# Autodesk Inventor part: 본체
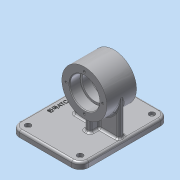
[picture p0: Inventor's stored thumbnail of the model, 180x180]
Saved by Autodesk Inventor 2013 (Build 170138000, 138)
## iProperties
Created: 2019-09
Part Number: 본체
Material: 알루미늄 6061
Document SubType Name: Modeling
Designer: Administrator
Density: 2.71 g/cm^3
Mass: 556.668 g
Surface Area: 495.884 cm^2
Volume: 205.413 cm^3
Author: Administrator
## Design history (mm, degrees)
sketch "스케치1"
  geometry: C1 r 32 at (0, 0); 1 further point
  constraints: 1 centre point, 1 coincident
  dimensions: "d0" = 64 diameter of C1
extrude "돌출1" new body sketch "스케치1" stored distance "d1" = 42; taper "d2" = 0 deg
hole "구멍1" diameter "d5" = 36; stored, may be unused: countersink angle "d9" = 90 deg, drill point angle "d11" = 118 deg; dims "d6" = 6, "d7" = 42, "d8" = 15, "d10" = 8, "d12" = 10, "d13" = 10
sketch "스케치2"
  geometry: C1 r 18 at (0, 0) reference; C2 r 32 at (0, 0) reference; C3 r 21 at (0, 0)
  constraints: 1 centre point, 1 coincident
  dimensions: "d14" = 42 diameter of C3
extrude "돌출2" cut sketch "스케치2" distance "d15" = 15; taper "d16" = 0 deg
sketch "스케치3"
  geometry: C1 r 21 at (0, 0) reference; 1 further point
  constraints: 1 vertical alignment
  dimensions: "d17" = 26 distance of point (0, 26) C1.centre
hole "구멍2" sketch "스케치3" at (0, 26) diameter "d18" = 3.242; stored, may be unused: countersink angle "d22" = 90 deg, drill point angle "d24" = 118 deg; dims "d19" = 8, "d20" = 42, "d21" = 15, "d23" = 10
chamfer "모따기1" distance "d28" = 1; stored, may be unused: second distance "d29" = 2, angle "d30" = 45 deg
fillet "모깎기1" dims "d31" = 0.3
sketch "스케치4"
  geometry: L1 (-62, -50)-(36, -50); L2 (36, -50)-(36, -59); L3 (36, -59)-(-62, -59); L4 (-62, -59)-(-62, -50); 1 further point
  constraints: 8 end point, 2 parallel, 1 horizontal, 1 perpendicular
  dimensions: "d32" = 59 distance from line of L3 point (0, 0); "d33" = 9 distance of L1.end L2.end; "d34" = 98 distance of L2.end L3.end; "d35" = 36 distance from line of L2 point (0, 0)
extrude "돌출3" join sketch "스케치4" stored distance "d36" = 126; taper "d37" = 0 deg
fillet "모깎기2" dims "d38" = 12
fillet "모깎기3" dims "d39" = 3
sketch "스케치5"
  geometry: A1 r 9 centre (0, 9) between (-9, 9) and (0, 0) reference; A2 r 9 centre (74, 9) between (74, 0) and (83, 9) reference; A3 r 9 centre (74, 111) between (83, 111) and (74, 120) reference; A4 r 9 centre (0, 111) between (0, 120) and (-9, 111) reference; 5 further points
  constraints: 4 coincident
hole "구멍3" sketch "스케치5" at (0, 111), (74, 111), (0, 9), (74, 9) diameter "d40" = 4.5; stored, may be unused: countersink angle "d44" = 90 deg, drill point angle "d46" = 118 deg; dims "d41" = 8, "d42" = 8, "d43" = 4.4, "d45" = 10
sketch "스케치6"
  geometry: L1 (18, 64)-(82, 64); L2 (82, 64)-(82, 56); L3 (82, 56)-(18, 56); L4 (18, 56)-(18, 64); 2 further points
  constraints: 8 end point, 2 parallel, 1 horizontal, 1 horizontal alignment, 1 midpoint, 1 perpendicular
  dimensions: "d47" = 64 distance of L1.start L1.end; "d49" = 8 distance of L3.end L1.start; "d50" = 32 distance from line of point (50, 60) L2
extrude "돌출4" join sketch "스케치6" stored distance "d51" = 126; taper "d52" = 0 deg
sketch "스케치7"
  geometry: L1 (46, 43)-(54, 43); L2 (54, 43)-(54, 77); L3 (54, 77)-(46, 77); L4 (46, 77)-(46, 43); 3 further points
  constraints: 8 end point, 2 midpoint, 2 parallel, 1 horizontal, 1 horizontal alignment, 1 perpendicular, 1 vertical alignment
  dimensions: "d53" = 8 distance of L3.end L2.end; "d54" = 34 distance of L2.end L1.end
extrude "돌출5" join sketch "스케치7" stored distance "d55" = 126; taper "d56" = 0 deg
fillet "모깎기4" dims "d57" = 3
fillet "모깎기5" dims "d58" = 3
fillet "모깎기6" dims "d59" = 3
sketch "스케치8"
  geometry: L1 (74, 3)-(0, 3) reference; L2 (-12, -9)-(-12, -111) reference; 2 further points
  constraints: 1 other
  dimensions: "d60" = 63 distance from line of L1 point (-2, -60); "d61" = 10 distance from line of L2 point (-2, -60)
feature "엠보싱1" sketch "스케치8" dims "d62" = 0.5, "d63" = 0
node "솔리드1"
pattern_circular "원형 패턴1" dims angle "d26" = 360 deg
mirror "대칭1"
